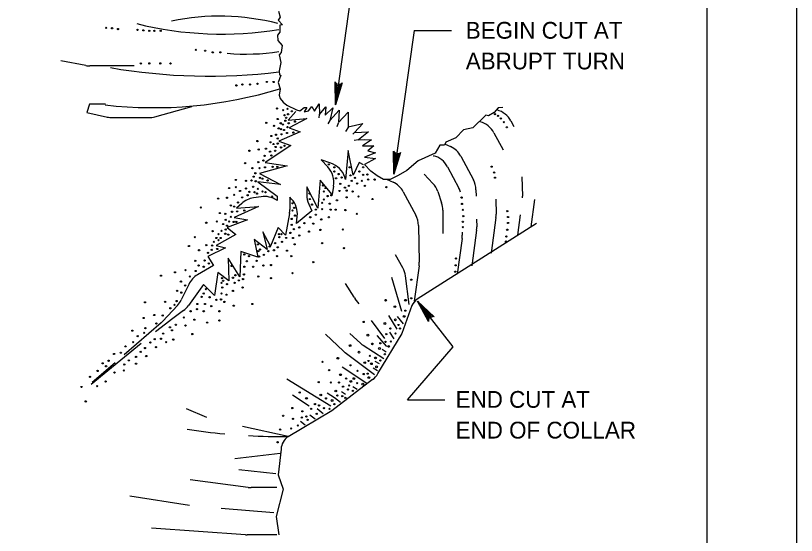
# Model space of a CAD drawing. Extents: x 639115 to 640019, y 298285 to 298879.
# Drawn here: x 639816.1 to 639956, y 298555.2 to 298648.2 of the extents above; entities that cross this region are included whole.
import ezdxf

# ---------------------------------------------------------------- set-up
doc = ezdxf.new("R2010")
doc.units = 0
doc.layers.add('1', color=7, linetype='Continuous')
doc.layers.add('PLT-BNDY', color=7, linetype='Continuous')

msp = doc.modelspace()

# ---------------------------------------------------------------- linework, layer by layer
at = {"layer": '1'}
for p, q in [((639877.88, 298663.7), (639873.44, 298632.24)), ((639887.55, 298645.52), (639883.92, 298619.79)), ((639887.55, 298645.52), (639894.25, 298645.52)), ((639828.7, 298639.25), (639824.22, 298640.09)), ((639837.4, 298639.19), (639829.44, 298639.19)), ((639841.1, 298630.09), (639847.7, 298631.91)), ((639902.4, 298631.31), (639902.41, 298631.3)), ((639833.44, 298629.94), (639840.04, 298629.94)), ((639870.54, 298630.47), (639870.47, 298629.87)), ((639872.44, 298629.41), (639872.08, 298628.84)), ((639904.88, 298629.34), (639905.41, 298628.35)), ((639873.95, 298628.96), (639873.71, 298628.31)), ((639875.77, 298628.28), (639875.24, 298627.44)), ((639899.37, 298629.18), (639899.38, 298629.18)), ((639876.89, 298627.25), (639876.59, 298626.95)), ((639901.85, 298627.21), (639903.47, 298624.19)), ((639877.57, 298625.93), (639876.83, 298625.85)), ((639893.01, 298625.25), (639894.08, 298624.75)), ((639891.04, 298623.12), (639891.05, 298623.12)), ((639895.91, 298623.01), (639898.16, 298618.82)), ((639893.52, 298621.15), (639895.58, 298617.31)), ((639889.37, 298619.79), (639890.92, 298618.13)), ((639882.7, 298618.88), (639883.77, 298618.38)), ((639906.87, 298619.32), (639906.94, 298615.86)), ((639891.77, 298616.72), (639892.48, 298614.67)), ((639898.63, 298617.01), (639898.65, 298615.85)), ((639860.12, 298615.78), (639858.76, 298615.58)), ((639885.61, 298616.65), (639887.85, 298612.46)), ((639902.21, 298615.32), (639902.25, 298612.66)), ((639909.13, 298615.26), (639908.46, 298610.4)), ((639892.7, 298613.36), (639892.7, 298609.18)), ((639906.53, 298612.51), (639906.04, 298608.88)), ((639898.73, 298611.78), (639898.76, 298610.4)), ((639902.21, 298612.07), (639901.34, 298605.7)), ((639909.47, 298610.97), (639888.11, 298597.42)), ((639888.33, 298610.64), (639888.46, 298604.04)), ((639898.72, 298609.79), (639897.86, 298603.43)), ((639896.17, 298609.41), (639896.18, 298608.89)), ((639896.15, 298608.27), (639895.28, 298601.91)), ((639885.52, 298603.03), (639884.22, 298605.4)), ((639888.42, 298603.42), (639887.55, 298597.06)), ((639885.36, 298595.24), (639883.54, 298601.3)), ((639886.64, 298596.46), (639885.98, 298601.61)), ((639847.16, 298600.09), (639845.81, 298597.3)), ((639876.78, 298597.82), (639875.28, 298600.24)), ((639877.67, 298596.6), (639876.98, 298597.52)), ((639845.13, 298596.32), (639842.5, 298593.5)), ((639894.52, 298588.88), (639888.16, 298597.06)), ((639846.25, 298595.4), (639843.84, 298593.6)), ((639884.52, 298592.06), (639883.01, 298594.49)), ((639885.62, 298593.05), (639884.56, 298594.33)), ((639842.2, 298593.21), (639835.59, 298587.48)), ((639843.76, 298593.55), (639841.23, 298591.57)), ((639882.32, 298590.39), (639879.89, 298593.64)), ((639883.95, 298590.32), (639883.2, 298591.53)), ((639874.9, 298588.11), (639871.64, 298591.15)), ((639877.91, 298589.56), (639876.04, 298591.3)), ((639882.67, 298588.95), (639880.92, 298590.92)), ((639838.67, 298589.51), (639829.71, 298582.14)), ((639882.1, 298586.76), (639878.44, 298589.15)), ((639886.34, 298579.45), (639894.52, 298588.88)), ((639880.43, 298583.88), (639875.21, 298587.85)), ((639882.55, 298587.97), (639881.79, 298588.42)), ((639833.96, 298586.07), (639829.86, 298582.52)), ((639881.34, 298585.85), (639880.58, 298586.3)), ((639879.07, 298582.36), (639874.67, 298585.24)), ((639880.96, 298584.64), (639880.2, 298585.09)), ((639872.63, 298578.27), (639864.75, 298583.12)), ((639877.32, 298581.3), (639876.57, 298581.76)), ((639871.98, 298580.7), (639873.27, 298579.86)), ((639875.28, 298580.39), (639874.52, 298580.85)), ((639868.76, 298578.27), (639865.73, 298580.24)), ((639873.27, 298579.86), (639874.33, 298579.03)), ((639886.34, 298579.45), (639893.04, 298579.45)), ((639850.43, 298576.27), (639846.79, 298577.82)), ((639870.16, 298577.89), (639871.23, 298576.98)), ((639868.88, 298576.76), (639869.79, 298576)), ((639867.21, 298575.62), (639868.04, 298574.94)), ((639864.96, 298572.84), (639856.77, 298574.66)), ((639863.54, 298569.79), (639855.41, 298568.88)), ((639862.77, 298566.17), (639856.11, 298566.91)), ((639857.83, 298563.76), (639847.4, 298565.09)), ((639862.93, 298563.73), (639858.34, 298563.73)), ((639847.29, 298560.54), (639836.64, 298562.21)), ((639862.4, 298559.18), (639853, 298559.96)), ((639857.33, 298555.25), (639840.5, 298556.45)), ((639862.93, 298555.24), (639857.62, 298555.24))]:
    msp.add_line(p, q, dxfattribs=at)
for points in [[(639940.03, 298300.23), (639940.03, 298864.23), (639154.03, 298864.23), (639154.03, 298300.23), (639940.03, 298300.23), (639940.03, 298326.59), (639740.03, 298326.59), (639740.03, 298391.26), (639940.03, 298391.26), (639940.03, 298420.23), (639740.03, 298420.23), (639740.03, 298300.23), (639818.83, 298300.23), (639818.83, 298326.59), (639818.83, 298300.23), (639895.83, 298300.23), (639895.83, 298326.59), (639895.83, 298314.27), (639940.03, 298314.27)], [(639863.27, 298648.96), (639863.57, 298647.9), (639863.19, 298647.37), (639863.95, 298646.53), (639863.5, 298646.46), (639863.5, 298645.25), (639863.04, 298644.72), (639863.12, 298643.73), (639863.88, 298642.82), (639863.73, 298641.61), (639863.35, 298641.16), (639863.65, 298639.79), (639863.35, 298638.28), (639863.42, 298637.59), (639863.65, 298637.52), (639863.19, 298636.23), (639863.57, 298635.09), (639863.35, 298633.96), (639863.57, 298633.35), (639864.1, 298632.67), (639864.71, 298632.14), (639866.45, 298631.31), (639867.09, 298631.12)], [(639874.46, 298635.99), (639874.16, 298635.89), (639873.44, 298632.24), (639874.46, 298635.99), (639874.66, 298636.17), (639873.44, 298632.24), (639873.78, 298635.94), (639873.52, 298636.11), (639873.44, 298632.24), (639873.37, 298636.35), (639873.52, 298636.11)], [(639832.25, 298632.37), (639829.37, 298632.37), (639828.91, 298630.85), (639832.58, 298630.04)], [(639867.09, 298631.12), (639867.82, 298631.77), (639868.31, 298631.77), (639867.82, 298630.96), (639868.64, 298631.17), (639869.2, 298631.91), (639869.68, 298631.07), (639870.52, 298632.4), (639870.61, 298630.52), (639871.74, 298631.84), (639871.59, 298630.36), (639872.99, 298631.68), (639872.46, 298629.43), (639874.12, 298631.27), (639873.99, 298629.05), (639875.75, 298630.93), (639875.71, 298628.31), (639878.35, 298628.88), (639876.85, 298627.25), (639879.39, 298627.4), (639877.57, 298625.96), (639878.71, 298626.04), (639879.88, 298625.96), (639878.29, 298624.87), (639880.3, 298624.87), (639879.28, 298623.96), (639880.64, 298623.62), (639878.68, 298622.88), (639880.64, 298622.63), (639878.68, 298621.52)], [(639866.34, 298631), (639864.98, 298629.49), (639868.31, 298629.79), (639865.13, 298628.12), (639867.1, 298627.37), (639863.31, 298625.7), (639865.43, 298624.94), (639860.88, 298621.91), (639864.82, 298621.31), (639859.82, 298619.94), (639863.61, 298617.97), (639859.52, 298618.43), (639863.01, 298615.85), (639863.01, 298615.09), (639862.92, 298615.15)], [(639903.42, 298631.76), (639902.59, 298631.68), (639901.91, 298630.85), (639900.85, 298630.25), (639900.39, 298630.4), (639898.05, 298628.12), (639896.38, 298627.75), (639895.01, 298626.31), (639893.2, 298625.55), (639892.97, 298625.02), (639892.14, 298625.02), (639891.3, 298623.58), (639888.27, 298622.21), (639886.23, 298620.47), (639884.71, 298619.56), (639883.27, 298618.88), (639882.06, 298618.88), (639880.92, 298619.49), (639879.79, 298620.32), (639878.68, 298621.52)], [(639878.46, 298621.46), (639877.7, 298621.91), (639876.64, 298619.64), (639875.73, 298624.03), (639875.28, 298618.88), (639875.15, 298619.26)], [(639884.94, 298623.54), (639884.64, 298623.44), (639883.92, 298619.79), (639884.94, 298623.54), (639885.13, 298623.72), (639883.92, 298619.79), (639884.25, 298623.49), (639884, 298623.67), (639883.92, 298619.79), (639883.84, 298623.9), (639884, 298623.67)], [(639872.62, 298621.79), (639870.88, 298622.37), (639872.08, 298621.1)], [(639873.12, 298617.66), (639872.85, 298616.15), (639870.73, 298618.73), (639870.28, 298613.73), (639868.31, 298617.52), (639868.31, 298616.12)], [(639865.6, 298615.35), (639865.28, 298615.7), (639865.28, 298613.48)], [(639856.65, 298614.57), (639855.73, 298613.73), (639859.67, 298614.03), (639855.28, 298612.06), (639857.7, 298611.61), (639854.07, 298610.24), (639855.58, 298609.03), (639852.1, 298607.06), (639853.76, 298606.61), (639850.58, 298605.09), (639851.63, 298603.47), (639848.76, 298601.81)], [(639868.68, 298614.45), (639869.22, 298613.27), (639866.49, 298611), (639866.62, 298612.26)], [(639865.22, 298612.77), (639864.52, 298608.88), (639863.16, 298610.24), (639861.79, 298606.91), (639860.43, 298609.49), (639861.19, 298606.3), (639858.91, 298608.12), (639859.52, 298604.94), (639856.49, 298606), (639856.34, 298601.46), (639854.22, 298604.79), (639854.37, 298600.7), (639852.4, 298602.21), (639851.79, 298598.12), (639849.82, 298600.09), (639847.12, 298596.29)], [(639887.11, 298596.31), (639885.32, 298591.3), (639881.01, 298584.11)], [(639890.15, 298593.72), (639890.28, 298594), (639888.16, 298597.06), (639890.15, 298593.72), (639890.13, 298593.46), (639888.16, 298597.06), (639890.58, 298594.24), (639890.88, 298594.31), (639888.16, 298597.06), (639891.16, 298594.25), (639890.88, 298594.31)], [(639880.08, 298583.05), (639872.82, 298577.44), (639864.95, 298572.83)], [(639863.72, 298570.59), (639863.16, 298566), (639864.07, 298563.42), (639862.85, 298558.57), (639863.31, 298555.24)]]:
    msp.add_lwpolyline(points, dxfattribs=at)
for centre, radius in [((639832.37, 298646), 0.111), ((639833.43, 298645.93), 0.111), ((639834.49, 298645.78), 0.111), ((639837.98, 298645.63), 0.111), ((639839.04, 298645.55), 0.111), ((639840.1, 298645.47), 0.111), ((639841.01, 298645.47), 0.111), ((639842.14, 298645.47), 0.111), ((639848.43, 298642.06), 0.111), ((639850.1, 298641.91), 0.111), ((639851.46, 298641.61), 0.111), ((639852.83, 298641.61), 0.111), ((639838.58, 298639.64), 0.111), ((639840.1, 298639.64), 0.111), ((639842.07, 298639.64), 0.111), ((639843.89, 298639.64), 0.111), ((639861.16, 298636.31), 0.111), ((639862.37, 298636.31), 0.111), ((639855.71, 298635.7), 0.111), ((639856.77, 298635.85), 0.111), ((639858.13, 298635.85), 0.111), ((639859.49, 298636), 0.111), ((639862.96, 298631.57), 0.111), ((639864.09, 298631.27), 0.111), ((639864.85, 298631.5), 0.111), ((639865.63, 298631.06), 0.111), ((639863.11, 298629.68), 0.111), ((639864.32, 298630.36), 0.111), ((639864.47, 298629.37), 0.111), ((639864.62, 298629.91), 0.111), ((639864.96, 298630.53), 0.111), ((639866.21, 298629.22), 0.111), ((639902.03, 298630.55), 0.111), ((639902.56, 298630.25), 0.111), ((639903.09, 298629.79), 0.111), ((639861.06, 298629), 0.111), ((639862.43, 298628.47), 0.111), ((639863.26, 298628.01), 0.111), ((639863.64, 298628.92), 0.111), ((639863.71, 298627.86), 0.111), ((639864.03, 298628.72), 0.111), ((639864.85, 298628.24), 0.111), ((639865.08, 298628.92), 0.111), ((639903.62, 298629.11), 0.111), ((639904.15, 298628.2), 0.111), ((639861.97, 298626.65), 0.111), ((639862.8, 298626.87), 0.111), ((639863.79, 298626.95), 0.111), ((639864.24, 298627.71), 0.111), ((639864.77, 298627.18), 0.111), ((639865.91, 298627.25), 0.111), ((639859.47, 298625.74), 0.111), ((639861.82, 298625.51), 0.111), ((639862.35, 298625.21), 0.111), ((639863.11, 298626.19), 0.111), ((639863.11, 298625.28), 0.111), ((639858.03, 298624), 0.111), ((639859.7, 298624.22), 0.111), ((639860.99, 298624.37), 0.111), ((639861.74, 298623.84), 0.111), ((639862.65, 298624), 0.111), ((639862.73, 298624.68), 0.111), ((639863.71, 298624.6), 0.111), ((639864.32, 298624.9), 0.111), ((639860.53, 298622.25), 0.111), ((639860.76, 298623.09), 0.111), ((639861.97, 298623.16), 0.111), ((639857.27, 298621.8), 0.111), ((639858.56, 298620.89), 0.111), ((639859.62, 298621.95), 0.111), ((639859.85, 298620.89), 0.111), ((639860.83, 298621.04), 0.111), ((639862.2, 298621.12), 0.111), ((639863.03, 298621.12), 0.111), ((639872.27, 298621.57), 0.111), ((639873.26, 298621.04), 0.111), ((639875.99, 298621.04), 0.111), ((639878.41, 298621.04), 0.111), ((639901.43, 298621.15), 0.111), ((639858.79, 298619.37), 0.111), ((639859.09, 298619.98), 0.111), ((639873.26, 298620.28), 0.111), ((639874.02, 298619.83), 0.111), ((639876.14, 298619.6), 0.111), ((639877.73, 298620.28), 0.111), ((639878.41, 298619.68), 0.111), ((639879.17, 298619.75), 0.111), ((639901.88, 298620.09), 0.111), ((639855.61, 298618.77), 0.111), ((639857.43, 298618.62), 0.111), ((639858.41, 298618.69), 0.111), ((639859.17, 298618.54), 0.111), ((639859.93, 298619.15), 0.111), ((639860.38, 298619), 0.111), ((639861.29, 298618.69), 0.111), ((639873.56, 298619.07), 0.111), ((639874.32, 298618.09), 0.111), ((639874.55, 298619.22), 0.111), ((639876.37, 298618.62), 0.111), ((639876.97, 298619.15), 0.111), ((639877.35, 298618.16), 0.111), ((639878.18, 298618.62), 0.111), ((639879.32, 298618.84), 0.111), ((639880.46, 298618.84), 0.111), ((639902.03, 298619.18), 0.111), ((639854.4, 298617.33), 0.111), ((639855.61, 298617.48), 0.111), ((639856.36, 298616.8), 0.111), ((639857.43, 298617.25), 0.111), ((639858.03, 298616.65), 0.111), ((639858.71, 298617.56), 0.111), ((639858.94, 298616.57), 0.111), ((639859.55, 298617.18), 0.111), ((639860.38, 298616.72), 0.111), ((639860.91, 298616.57), 0.111), ((639871.21, 298617.78), 0.111), ((639871.37, 298616.72), 0.111), ((639871.67, 298617.33), 0.111), ((639874.17, 298616.8), 0.111), ((639875.15, 298617.4), 0.111), ((639875.46, 298616.87), 0.111), ((639875.84, 298617.71), 0.111), ((639876.52, 298616.72), 0.111), ((639878.71, 298617.71), 0.111), ((639882.58, 298617.48), 0.111), ((639852.43, 298615.43), 0.111), ((639854.02, 298615.59), 0.111), ((639855.3, 298616.12), 0.111), ((639856.74, 298615.66), 0.111), ((639857.73, 298616.04), 0.111), ((639859.4, 298616.34), 0.111), ((639862.12, 298615.81), 0.111), ((639868.79, 298616.34), 0.111), ((639868.87, 298615.36), 0.111), ((639871.37, 298615.28), 0.111), ((639872.05, 298615.89), 0.111), ((639872.73, 298616.04), 0.111), ((639875.46, 298615.66), 0.111), ((639877.58, 298615.81), 0.111), ((639880.08, 298615.36), 0.111), ((639896.05, 298615.62), 0.111), ((639849.32, 298613.84), 0.111), ((639854.7, 298614.22), 0.111), ((639855.3, 298614), 0.111), ((639855.99, 298614.75), 0.111), ((639865.76, 298614.6), 0.111), ((639869.24, 298614.37), 0.111), ((639871.06, 298614.68), 0.111), ((639872.43, 298614.53), 0.111), ((639873.71, 298615.13), 0.111), ((639896.12, 298614.49), 0.111), ((639852.73, 298612.86), 0.111), ((639853.71, 298612.71), 0.111), ((639854.93, 298613.09), 0.111), ((639855.83, 298613.16), 0.111), ((639857.12, 298613.31), 0.111), ((639865.76, 298613.31), 0.111), ((639866.06, 298613.77), 0.111), ((639866.21, 298612.4), 0.111), ((639869.93, 298613.46), 0.111), ((639869.93, 298612.56), 0.111), ((639871.06, 298613.54), 0.111), ((639872.58, 298613.46), 0.111), ((639873.49, 298613.46), 0.111), ((639875.23, 298613.39), 0.111), ((639877.28, 298612.71), 0.111), ((639896.28, 298613.43), 0.111), ((639904.23, 298613.2), 0.111), ((639850.3, 298611.12), 0.111), ((639852.2, 298611.34), 0.111), ((639853.79, 298611.65), 0.111), ((639854.4, 298611.34), 0.111), ((639854.7, 298612.18), 0.111), ((639855.23, 298611.27), 0.111), ((639855.68, 298611.27), 0.111), ((639865.61, 298611.8), 0.111), ((639867.88, 298611.04), 0.111), ((639868.94, 298612.1), 0.111), ((639870.91, 298611.72), 0.111), ((639872.27, 298612.1), 0.111), ((639896.28, 298611.3), 0.111), ((639896.35, 298612.29), 0.111), ((639904.38, 298612.14), 0.111), ((639904.38, 298611.08), 0.111), ((639851.44, 298609.6), 0.111), ((639853.03, 298609.68), 0.111), ((639853.33, 298610.89), 0.111), ((639853.79, 298609.9), 0.111), ((639854.02, 298610.59), 0.111), ((639865.61, 298610.74), 0.111), ((639865.99, 298609.98), 0.111), ((639866.97, 298610.28), 0.111), ((639869.47, 298610.96), 0.111), ((639870.76, 298609.83), 0.111), ((639874.78, 298609.9), 0.111), ((639896.28, 298610.32), 0.111), ((639904.23, 298609.87), 0.111), ((639848.26, 298608.54), 0.111), ((639852.12, 298608.39), 0.111), ((639852.5, 298609.07), 0.111), ((639852.88, 298608.39), 0.111), ((639853.71, 298609.15), 0.111), ((639854.24, 298608.99), 0.111), ((639863.34, 298609.07), 0.111), ((639863.41, 298608.54), 0.111), ((639863.79, 298609.07), 0.111), ((639864.62, 298608.39), 0.111), ((639865.38, 298609.3), 0.111), ((639865.84, 298608.39), 0.111), ((639866.97, 298608.84), 0.111), ((639868.71, 298609.53), 0.111), ((639904.08, 298608.65), 0.111), ((639847.2, 298606.95), 0.111), ((639850.3, 298607.1), 0.111), ((639851.36, 298607.03), 0.111), ((639851.67, 298607.71), 0.111), ((639852.5, 298608.01), 0.111), ((639859.55, 298607.25), 0.111), ((639861.67, 298606.87), 0.111), ((639862.65, 298607.48), 0.111), ((639863.87, 298607.71), 0.111), ((639866.14, 298607.25), 0.111), ((639871.06, 298607.48), 0.111), ((639904, 298607.74), 0.111), ((639849.02, 298606.19), 0.111), ((639850.61, 298605.74), 0.111), ((639851.29, 298606.27), 0.111), ((639852.27, 298606.42), 0.111), ((639857.12, 298605.43), 0.111), ((639859.62, 298606.04), 0.111), ((639859.93, 298606.34), 0.111), ((639861.44, 298606.04), 0.111), ((639862.43, 298606.19), 0.111), ((639863.11, 298606.72), 0.111), ((639864.77, 298606.12), 0.111), ((639875, 298606.57), 0.111), ((639848.33, 298604.3), 0.111), ((639850, 298604.37), 0.111), ((639857.58, 298604.22), 0.111), ((639857.96, 298605.13), 0.111), ((639859.32, 298604.3), 0.111), ((639859.77, 298605.06), 0.111), ((639860.61, 298605.36), 0.111), ((639862.96, 298605.13), 0.111), ((639865.53, 298605.13), 0.111), ((639869.47, 298604.07), 0.111), ((639895.06, 298604.71), 0.111), ((639846.59, 298602.63), 0.111), ((639848.94, 298603.46), 0.111), ((639849.85, 298603.24), 0.111), ((639850.76, 298603.84), 0.111), ((639854.85, 298603.39), 0.111), ((639857.12, 298603.24), 0.111), ((639858.71, 298603.24), 0.111), ((639860.53, 298603.46), 0.111), ((639861.9, 298603.54), 0.111), ((639894.99, 298603.5), 0.111), ((639842.2, 298601.65), 0.111), ((639844.7, 298602.25), 0.111), ((639847.35, 298601.49), 0.111), ((639848.41, 298602.48), 0.111), ((639853.11, 298601.19), 0.111), ((639855.08, 298601.27), 0.111), ((639855.53, 298601.72), 0.111), ((639857.05, 298601.87), 0.111), ((639859.62, 298601.49), 0.111), ((639861.9, 298601.19), 0.111), ((639865.76, 298602.1), 0.111), ((639894.91, 298602.36), 0.111), ((639845.76, 298600.59), 0.111), ((639846.52, 298599.9), 0.111), ((639853.03, 298600.36), 0.111), ((639853.33, 298600.74), 0.111), ((639854.02, 298600.13), 0.111), ((639855.38, 298600.36), 0.111), ((639856.14, 298600.81), 0.111), ((639856.9, 298601.04), 0.111), ((639887.03, 298600.93), 0.111), ((639845.08, 298598.92), 0.111), ((639845.83, 298598.62), 0.111), ((639849.85, 298598.46), 0.111), ((639850.23, 298599.22), 0.111), ((639853.03, 298598.46), 0.111), ((639853.18, 298599.52), 0.111), ((639855.08, 298598.92), 0.111), ((639856.82, 298599.52), 0.111), ((639845, 298597.1), 0.111), ((639849.47, 298597.86), 0.111), ((639850.91, 298597.78), 0.111), ((639852.12, 298597.33), 0.111), ((639852.96, 298597.4), 0.111), ((639853.94, 298598.24), 0.111), ((639882.44, 298597.24), 0.159), ((639886, 298597.24), 0.159), ((639887.03, 298597.59), 0.111), ((639839.32, 298596.87), 0.111), ((639842.95, 298596.95), 0.111), ((639843.86, 298595.81), 0.111), ((639844.62, 298596.42), 0.111), ((639848.64, 298595.66), 0.111), ((639848.71, 298596.57), 0.111), ((639850.08, 298596.57), 0.111), ((639851.21, 298596.19), 0.111), ((639853.56, 298596.95), 0.111), ((639855.23, 298596.27), 0.111), ((639858.56, 298596.57), 0.111), ((639884.11, 298596.1), 0.159), ((639840.99, 298594.6), 0.111), ((639842.5, 298594.52), 0.111), ((639847.5, 298595.28), 0.111), ((639849.85, 298595.28), 0.111), ((639852.65, 298595.28), 0.111), ((639885.77, 298594.36), 0.159), ((639885.97, 298595.39), 0.111), ((639839.09, 298594.07), 0.111), ((639841.36, 298593.08), 0.111), ((639844.85, 298592.86), 0.111), ((639846.29, 298594.15), 0.111), ((639848.18, 298593.77), 0.111), ((639850.46, 298593.24), 0.111), ((639852.65, 298593.62), 0.111), ((639878.51, 298593.37), 0.111), ((639882.31, 298593.08), 0.159), ((639884.18, 298593.75), 0.159), ((639884.75, 298592.82), 0.111), ((639837.05, 298591.8), 0.111), ((639839.17, 298591.42), 0.111), ((639839.39, 298592.25), 0.111), ((639843.79, 298592.4), 0.111), ((639844.17, 298591.87), 0.111), ((639846.59, 298592.71), 0.111), ((639883.3, 298592.2), 0.111), ((639885.01, 298592.2), 0.111), ((639838.03, 298590.81), 0.111), ((639841.06, 298590.28), 0.111), ((639842.2, 298590.36), 0.111), ((639842.58, 298591.27), 0.111), ((639844.39, 298590.21), 0.111), ((639847.8, 298591.19), 0.111), ((639879.27, 298591), 0.159), ((639882.55, 298591.17), 0.111), ((639884.2, 298591.29), 0.111), ((639835.83, 298588.99), 0.111), ((639837.2, 298589.75), 0.111), ((639839.32, 298588.69), 0.111), ((639840.3, 298589.68), 0.111), ((639841.29, 298588.84), 0.111), ((639843.11, 298589.75), 0.111), ((639876.07, 298589.13), 0.159), ((639880.06, 298589.43), 0.159), ((639881.34, 298588.61), 0.159), ((639881.49, 298589.55), 0.111), ((639882.41, 298589.79), 0.111), ((639882.99, 298588.98), 0.159), ((639883.38, 298589.87), 0.111), ((639833.79, 298587.63), 0.111), ((639835, 298587.86), 0.111), ((639838.56, 298588.01), 0.111), ((639839.55, 298587.25), 0.111), ((639877.67, 298587.96), 0.159), ((639879.62, 298587.3), 0.111), ((639882.3, 298587.58), 0.111), ((639831.74, 298585.96), 0.111), ((639832.8, 298586.42), 0.111), ((639836.44, 298586.49), 0.111), ((639837.73, 298587.1), 0.111), ((639837.73, 298585.89), 0.111), ((639871.14, 298586.22), 0.111), ((639873.88, 298586.86), 0.159), ((639878.7, 298586.08), 0.159), ((639879.38, 298586.38), 0.111), ((639879.89, 298585.88), 0.159), ((639880.62, 298586.93), 0.159), ((639881.5, 298586.47), 0.111), ((639830.83, 298584.6), 0.111), ((639832.35, 298585.43), 0.111), ((639835.53, 298584.68), 0.111), ((639835.61, 298585.74), 0.111), ((639872.32, 298584.75), 0.111), ((639876.14, 298585.6), 0.111), ((639877.4, 298584.62), 0.111), ((639880.82, 298585.32), 0.159), ((639829.47, 298583.54), 0.111), ((639833.86, 298584.3), 0.111), ((639874.36, 298583.91), 0.159), ((639875.36, 298583.22), 0.111), ((639876.76, 298583.22), 0.159), ((639878.51, 298584.03), 0.111), ((639879.23, 298584.11), 0.111), ((639879.44, 298583.4), 0.159), ((639827.95, 298581.72), 0.111), ((639830.76, 298581.87), 0.111), ((639832.27, 298582.71), 0.111), ((639870.45, 298582.58), 0.111), ((639872.62, 298582.52), 0.111), ((639874.08, 298582.52), 0.111), ((639874.82, 298581.78), 0.111), ((639875.9, 298581.98), 0.111), ((639876.2, 298582.72), 0.159), ((639877.33, 298582.4), 0.111), ((639878.35, 298582.23), 0.159), ((639867.04, 298580.74), 0.111), ((639870.82, 298580.29), 0.159), ((639873.5, 298581), 0.159), ((639875.71, 298581.27), 0.111), ((639876.57, 298581.02), 0.111), ((639828.71, 298579.14), 0.111), ((639868.26, 298579.69), 0.159), ((639871.76, 298579.68), 0.111), ((639872.85, 298579.3), 0.159), ((639873.8, 298580.19), 0.111), ((639874.68, 298580.08), 0.111), ((639875.21, 298579.79), 0.111), ((639865.72, 298577.95), 0.111), ((639869.1, 298577.8), 0.111), ((639869.77, 298578.66), 0.111), ((639870.52, 298578.42), 0.111), ((639871.41, 298577.94), 0.111), ((639872.38, 298577.81), 0.111), ((639873.25, 298578.64), 0.111), ((639864.08, 298576.58), 0.111), ((639865.84, 298576.03), 0.111), ((639867.43, 298576.24), 0.111), ((639867.51, 298577.36), 0.111), ((639868.24, 298576.45), 0.111), ((639870.09, 298576.91), 0.111), ((639866.72, 298574.83), 0.111), ((639868.47, 298575.85), 0.111), ((639863.54, 298574.1), 0.111), ((639865.51, 298574.29), 0.111), ((639863.09, 298571.83), 0.111)]:
    msp.add_circle(centre, radius, dxfattribs=at)
for centre, radius, start, end in [((639852.63, 298605.97), 42.13, 75.5362, 101.7359), ((639853.17, 298708.32), 63.44, 256.0295, 279.1987), ((639857.48, 298678.38), 37.08, 264.7143, 279.0414), ((639829.44, 298643.19), 4, 259.3803, 270), ((639850.79, 298740.45), 103.09, 260.1487, 276.9727), ((639840.94, 298708.33), 76.62, 263.4246, 287.0893), ((639901.36, 298627.44), 4, 28.2174, 74.7449), ((639833.44, 298633.94), 4, 257.4712, 270), ((639840.04, 298633.94), 4, 270, 285.4612), ((639898.33, 298625.32), 4, 28.2174, 74.7449), ((639892.38, 298621.12), 4, 28.2174, 64.9831), ((639889.99, 298619.26), 4, 28.2174, 74.7449), ((639869.18, 298618.35), 4, 350.1342, 43.3634), ((639871.36, 298617.99), 4, 18.4349, 71.5651), ((639882.08, 298614.76), 4, 28.2174, 64.9831), ((639887.99, 298615.41), 4, 19.179, 43.0251), ((639894.63, 298616.93), 4, 1.1017, 28.2174), ((639892.06, 298615.42), 4, 17.4027, 28.2174), ((639859.35, 298611.62), 4, 98.427, 132.5104), ((639860.7, 298611.82), 4, 56.3099, 98.427), ((639862.64, 298612.66), 4, 354.2894, 42.2737), ((639872.31, 298616.12), 4, 180, 204.7751), ((639902.94, 298615.78), 4, 356.9022, 1.1017), ((639888.7, 298613.36), 4, 0, 19.179), ((639861.28, 298613.48), 4, 349.8753, 0), ((639898.25, 298612.61), 4, 352.2348, 0.7345), ((639884.33, 298610.57), 4, 1.1017, 28.2174), ((639894.76, 298610.33), 4, 352.2348, 1.1017), ((639892.18, 298608.81), 4, 352.2348, 1.1017), ((639882.01, 298601.1), 4, 7.3058, 28.8108), ((639884.46, 298603.96), 4, 352.2348, 1.1017), ((639850.76, 298598.35), 4, 119.9816, 154.1474), ((639842.21, 298599.05), 4, 316.9749, 334.1474), ((639880.18, 298599.92), 4, 211.7014, 216.8699), ((639889.61, 298595.06), 2.79, 122.3998, 153.4349), ((639843.86, 298598.61), 4, 306.6341, 324.6052), ((639839.58, 298596.23), 4, 310.9144, 316.9749), ((639846.22, 298590.39), 4, 126.6341, 127.9542), ((639880.63, 298592.5), 4, 227.1211, 236.8215), ((639877.63, 298591.03), 4, 226.9749, 232.7447), ((639878.52, 298585.36), 2.79, 304.0193, 333.4349), ((639864.13, 298685.8), 112.96, 261.2325, 264.6529), ((639864.13, 298685.8), 112.96, 266.8123, 270.4222), ((639866.51, 298570.52), 2.79, 124.0193, 178.4732), ((639858.34, 298567.73), 4, 262.725, 270), ((639857.62, 298559.24), 4, 265.9144, 270)]:
    msp.add_arc(centre, radius, start, end, dxfattribs=at)
at = {"layer": 'PLT-BNDY'}
msp.add_lwpolyline([(639115.03, 298879.23), (639956.03, 298879.23), (639956.03, 298285.23), (639115.03, 298285.23)], close=True, dxfattribs=at)

# ---------------------------------------------------------------- texts
at = {"layer": '1'}
for s, height, p in [('BEGIN CUT AT', 2.9997, (639896.8, 298644.06)), ('ABRUPT TURN', 2.9997, (639896.8, 298638.57)), ('END CUT AT', 3, (639894.98, 298578)), ('END OF COLLAR', 2.9997, (639894.98, 298572.5))]:
    msp.add_text(s, height=height, dxfattribs=at).set_placement(p)

doc.saveas('drawing.dxf')
